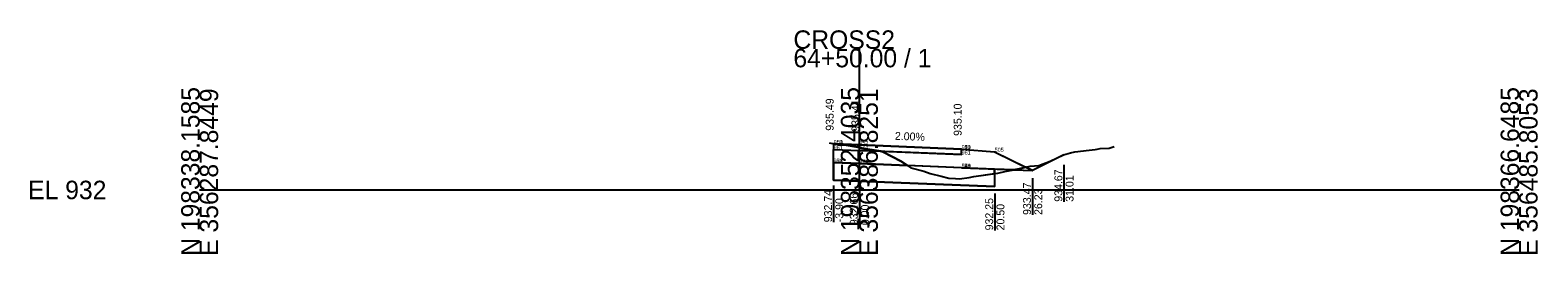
# Model space of a CAD drawing. Extents: x -26 to 203, y -10 to 14021.
# Drawn here: x -25.7 to 202.8, y 5490.3 to 5524.2 of the extents above; entities that cross this region are included whole.
import ezdxf

# ---------------------------------------------------------------- set-up
doc = ezdxf.new("R2010")
doc.units = 0
for name, color, linetype in [('Default', 7, 'Continuous'), ('P_E_XS_Ground', 7, 'Continuous'), ('P_XS', 7, 'Continuous'), ('P_XS_Bold', 7, 'Continuous'), ('P_XS_EAR_CommonGrnd', 7, 'Continuous'), ('P_XS_Lane', 7, 'Continuous'), ('P_XS_Rock', 7, 'Continuous')]:
    doc.layers.add(name, color=color, linetype=linetype)

msp = doc.modelspace()

# ---------------------------------------------------------------- linework, layer by layer
at = {"layer": 'Default'}
for p, q in [((100, 5500), (100, 5521.4)), ((0, 5500), (100, 5500)), ((100, 5500), (200, 5500))]:
    msp.add_line(p, q, dxfattribs=at)
at = {"layer": 'P_E_XS_Ground'}
for p, q in [((95.43, 5507.13), (96.93, 5506.86)), ((96.93, 5506.86), (97.64, 5506.85)), ((97.64, 5506.85), (98.31, 5506.72)), ((98.31, 5506.72), (100, 5506.43)), ((100, 5506.43), (100.39, 5506.36)), ((100.39, 5506.36), (101.56, 5506.16)), ((101.56, 5506.16), (102.96, 5505.92)), ((102.96, 5505.92), (103.56, 5505.8)), ((103.56, 5505.8), (106.27, 5504.37)), ((130.93, 5505.31), (131.99, 5505.61)), ((131.99, 5505.61), (132.67, 5505.8)), ((132.67, 5505.8), (134.82, 5506.05)), ((134.82, 5506.05), (135.74, 5506.15)), ((135.74, 5506.15), (136.05, 5506.2)), ((136.05, 5506.2), (136.5, 5506.31)), ((136.5, 5506.31), (137.84, 5506.35)), ((137.84, 5506.35), (138.64, 5506.57)), ((106.27, 5504.37), (107.78, 5503.35)), ((107.78, 5503.35), (109.78, 5502.83)), ((122.05, 5502.8), (124.22, 5503.2)), ((124.22, 5503.2), (125.9, 5503.62)), ((125.9, 5503.62), (127.19, 5503.71)), ((127.19, 5503.71), (128.92, 5504.38)), ((128.92, 5504.38), (130.93, 5505.31)), ((109.78, 5502.83), (110.71, 5502.5)), ((110.71, 5502.5), (112.39, 5502.09)), ((112.39, 5502.09), (113.57, 5501.78)), ((113.57, 5501.78), (114.59, 5501.74)), ((114.59, 5501.74), (115.2, 5501.69)), ((115.2, 5501.69), (116.62, 5501.91)), ((116.62, 5501.91), (117.33, 5502.04)), ((117.33, 5502.04), (120.97, 5502.53)), ((120.97, 5502.53), (122.05, 5502.8))]:
    msp.add_line(p, q, dxfattribs=at)
at = {"layer": 'P_XS'}
for p, q in [((96.1, 5506.98), (96.1, 5506.14)), ((96.1, 5506.14), (100, 5505.99)), ((96.1, 5504.14), (96.1, 5506.14)), ((115.5, 5505.37), (100, 5505.99)), ((115.5, 5505.37), (115.5, 5506.2)), ((96.1, 5504.14), (100, 5503.99)), ((96.1, 5504.14), (96.1, 5501.48)), ((115.5, 5503.37), (100, 5503.99)), ((115.5, 5503.37), (126.23, 5502.94)), ((120.5, 5503.17), (120.5, 5500.5)), ((96.1, 5501.48), (120.5, 5500.5))]:
    msp.add_line(p, q, dxfattribs=at)
at = {"layer": 'P_XS_EAR_CommonGrnd'}
for points in [[(96.1, 5507.01), (96.35, 5506.97), (96.1, 5506.98)], [(96.1, 5506.14), (100, 5505.99), (103.26, 5505.86), (102.96, 5505.92), (101.56, 5506.16), (100.39, 5506.36), (100, 5506.43), (98.31, 5506.72), (97.64, 5506.85), (96.93, 5506.86), (96.35, 5506.97), (96.1, 5506.98)], [(96.1, 5506.14), (100, 5505.99), (103.26, 5505.86), (103.56, 5505.8), (106.27, 5504.37), (107.27, 5503.7), (100, 5503.99), (96.1, 5504.14)], [(101.56, 5506.16), (102.96, 5505.92), (103.26, 5505.86), (115.5, 5505.37), (115.5, 5506.2), (100, 5506.82), (96.35, 5506.97), (96.93, 5506.86), (97.64, 5506.85), (98.31, 5506.72), (100, 5506.43), (100.39, 5506.36)], [(120.5, 5505.8), (125.21, 5503.45), (124.22, 5503.2), (123.41, 5503.05), (120.5, 5503.17), (115.5, 5503.37), (107.27, 5503.7), (106.27, 5504.37), (103.56, 5505.8), (103.26, 5505.86), (115.5, 5505.37), (115.5, 5506.2)], [(120.5, 5502.47), (120.5, 5500.5), (96.1, 5501.48), (96.1, 5504.14), (100, 5503.99), (107.27, 5503.7), (107.78, 5503.35), (109.78, 5502.83), (110.71, 5502.5), (112.39, 5502.09), (113.57, 5501.78), (114.59, 5501.74), (115.2, 5501.69), (116.62, 5501.91), (117.33, 5502.04)], [(107.27, 5503.7), (107.78, 5503.35), (109.78, 5502.83), (110.71, 5502.5), (112.39, 5502.09), (113.57, 5501.78), (114.59, 5501.74), (115.2, 5501.69), (116.62, 5501.91), (117.33, 5502.04), (120.5, 5502.47), (120.5, 5503.17), (115.5, 5503.37)], [(120.5, 5502.47), (120.97, 5502.53), (122.05, 5502.8), (123.41, 5503.05), (120.5, 5503.17)], [(123.41, 5503.05), (126.23, 5502.94), (125.21, 5503.45), (124.22, 5503.2)], [(131.01, 5505.33), (126.23, 5502.94), (125.21, 5503.45), (125.9, 5503.62), (127.19, 5503.71), (128.92, 5504.38), (130.93, 5505.31)]]:
    msp.add_lwpolyline(points, close=True, dxfattribs=at)
at = {"layer": 'P_XS_Lane'}
for p, q in [((96.1, 5506.98), (96.1, 5507.01)), ((96.1, 5506.98), (100, 5506.82)), ((100, 5506.82), (115.5, 5506.2)), ((115.5, 5506.2), (120.5, 5505.8)), ((120.5, 5505.8), (126.23, 5502.94)), ((131.01, 5505.33), (126.23, 5502.94))]:
    msp.add_line(p, q, dxfattribs=at)
at = {"layer": 'P_XS_Rock'}
for p, q in [((131.01, 5503.8), (131.01, 5498.21)), ((126.26, 5501.8), (126.26, 5496.21)), ((96.1, 5500.7), (96.1, 5495.1)), ((100, 5500.26), (100, 5494.66)), ((120.53, 5499.46), (120.53, 5493.87))]:
    msp.add_line(p, q, dxfattribs=at)

# ---------------------------------------------------------------- texts
at = {"layer": 'Default'}
for s, p in [('CROSS2', (90, 5521.4)), ('64+50.00 / 1', (90, 5518.6)), ('EL 932', (-26, 5498.6))]:
    msp.add_text(s, height=2.8, dxfattribs=at).set_placement(p)
for s, p in [('N 198338.1585', (0, 5490)), ('E 356287.8449', (2.8, 5490)), ('N 198352.4035', (100, 5490)), ('E 356386.8251', (102.8, 5490)), ('N 198366.6485', (200, 5490)), ('E 356485.8053', (202.8, 5490))]:
    msp.add_text(s, height=2.8, rotation=90, dxfattribs=at).set_placement(p)
at = {"layer": 'P_XS_Bold'}
for s, p in [('951', (96.1, 5506.98)), ('9', (96.1, 5506.98)), ('900', (96.1, 5506.98)), ('961', (96.1, 5506.14)), ('952', (100, 5506.82)), ('952', (100, 5506.82)), ('962', (100, 5505.99)), ('962', (100, 5505.99)), ('951', (115.5, 5506.2)), ('9', (115.5, 5506.2)), ('900', (115.5, 5506.2)), ('910', (115.5, 5506.2)), ('961', (115.5, 5505.37)), ('505', (120.5, 5505.8)), ('971', (96.1, 5504.14)), ('998', (96.1, 5504.14)), ('972', (100, 5503.99)), ('972', (100, 5503.99)), ('540', (115.5, 5503.37)), ('971', (115.5, 5503.37)), ('998', (115.5, 5503.37))]:
    msp.add_text(s, height=0.6, dxfattribs=at).set_placement(p)
at = {"layer": 'P_XS_Rock'}
for s, rotation, p in [('935.49', 90, (96.1, 5508.98)), ('935.41', 90, (100, 5508.82)), ('935.41', 90, (100, 5508.82)), ('935.41', 90, (100, 5508.82)), ('935.41', 90, (100, 5508.82)), ('935.10', 90, (115.5, 5508.2)), ('2.00%', 357.7094, (105.36, 5507.61)), ('933.47', 90, (126.01, 5496.21)), ('934.67', 90, (130.76, 5498.21)), ('31.01', 90, (132.46, 5498.21)), ('932.74', 90, (95.85, 5495.1)), ('-3.90', 90, (97.55, 5495.1)), ('932.66', 90, (99.75, 5494.66)), ('932.25', 90, (120.28, 5493.87)), ('26.23', 90, (127.71, 5496.21)), ('0.00', 90, (101.45, 5494.66)), ('20.50', 90, (121.98, 5493.87))]:
    msp.add_text(s, height=1.2, rotation=rotation, dxfattribs=at).set_placement(p)

doc.saveas('drawing.dxf')
